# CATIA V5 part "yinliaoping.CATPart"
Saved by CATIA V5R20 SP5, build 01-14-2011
Part number: 饮料瓶
Bounding box of the stored display mesh (mm): x -26 to 26, y -25.976 to 25.977, z 0 to 110
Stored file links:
  E:\180132104于洋\yinliaoping.CATPart
  C:\Program Files\Dassault Systemes\B20\intel_a\startup\materials\Catalog.CATMaterial
  C:\Program Files\Dassault Systemes\B20\intel_a\startup\materials\brushed_metal1.jpg
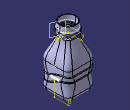
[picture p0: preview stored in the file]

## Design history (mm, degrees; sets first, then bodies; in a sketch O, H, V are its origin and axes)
Set1
  Sketch1 on xy-plane, origin (0, 0, 0), H (1, 0, 0), V (0, 1, 0)
    line L1 (25, 25) -> (25, -25)
    line L2 (25, -25) -> (-25, -25)
    line L3 (-25, -25) -> (-25, 25)
    line L4 (-25, 25) -> (25, 25)
    length L1 = 50
    length L4 = 50
    vertical: L1 V, L3 V
    horizontal: L2 H, L4 H
    equidistance: L1 L3 O, L2 L4 O
  Sketch2 on face of Pad1 from Sketch1.L3, origin (-25, 0, 0), H (0, -1, 0), V (0, 0, 1)
    spline S1 through (-40, 20) (-10, 30) (10, 20) (40, 30)
  Extrude1: Element1 Sketch2, Lim1 60, Lim2 60
  MultiSel1: CommonCtxFeats ({extract ExtractElem face of Pad1 from Sketch1.L3}; {extract ExtractElem face of Fillet1}; {extract ExtractElem face of Pad1 from Sketch1.L2}; {extract ExtractElem face of Fillet1}; {extract ExtractElem face of Pad1 from Sketch1.L1}; {extract ExtractElem face of Fillet1}; {extract ExtractElem face of Pad1 from Sketch1.L4}; {extract ExtractElem face of Fillet1})
  Join1: Elements ({intersect ToIntersect1 {extract ExtractElem face of Pad1 from Sketch1.L1}, ToIntersect2 Extrude1}; {intersect ToIntersect1 {extract ExtractElem face of Fillet1}, ToIntersect2 Extrude1}; {intersect ToIntersect1 {extract ExtractElem face of Pad1 from Sketch1.L4}, ToIntersect2 Extrude1}; {intersect ToIntersect1 {extract ExtractElem face of Fillet1}, ToIntersect2 Extrude1}; {intersect ToIntersect1 {extract ExtractElem face of Pad1 from Sketch1.L3}, ToIntersect2 Extrude1}; {intersect ToIntersect1 {extract ExtractElem face of Fillet1}, ToIntersect2 Extrude1}; {intersect ToIntersect1 {extract ExtractElem face of Pad1 from Sketch1.L2}, ToIntersect2 Extrude1}; {intersect ToIntersect1 {extract ExtractElem face of Fillet1}, ToIntersect2 Extrude1})
  Sketch3 on face of Pad1 from Sketch1.L1, origin (25, 0, 0), H (0, 1, 0), V (0, 0, 1)
    spline S1 through (-40, 40) (-20, 30) (10, 40) (40, 30)
  Extrude2: Element1 Sketch3, Lim1 60, Lim2 60
  MultiSel2: CommonCtxFeats ({extract ExtractElem face of Pad1 from Sketch1.L1}; {extract ExtractElem face of Fillet1}; {extract ExtractElem face of Pad1 from Sketch1.L4}; {extract ExtractElem face of Fillet1}; {extract ExtractElem face of Pad1 from Sketch1.L3}; {extract ExtractElem face of Fillet1}; {extract ExtractElem face of Pad1 from Sketch1.L2}; {extract ExtractElem face of Fillet1})
  Plane1: type Normal, Curve Join1, RefPoint vertex [face of MultiSel1 | face of MultiSel1]
  Circle1: type CtrRad, Start 0, End 180, Center vertex [face of MultiSel1 | face of MultiSel1], Support Plane1, Radius 1, FirstDirection (-1, 0, 0)
  Plane2: type Normal, Curve {intersect ToIntersect1 {extract ExtractElem face of Pad1 from Sketch1.L1}, ToIntersect2 Extrude2}, RefPoint vertex of MultiSel2
Body1 (main body), material "无"
  Pad1: profile Sketch1, direction (0, 0, 1), length 50
  Fillet1: on edge [face of Pad1 from Sketch1.L4 | face of Pad1 from Sketch1.L1]; edge [face of Pad1 from Sketch1.L1 | face of Pad1 from Sketch1.L2]; edge [face of Pad1 from Sketch1.L3 | face of Pad1 from Sketch1.L4]; edge [face of Pad1 from Sketch1.L2 | face of Pad1 from Sketch1.L3]
  Fillet2: on edge [start face of Pad1 | face of Pad1 from Sketch1.L4]
  Plane3: type Offset, RefPlane end face of Pad1, Offset 40, reversed
  Sketch4 on Plane3, origin (0, 0, 90), H (1, 0, 0), V (0, -1, 0)
    circle A1 centre (0, 0) radius 15
  Pad2: profile Sketch4, direction (0, 0, 1), length 20
  Sketch5 on end face of Pad1, origin (0, 0, 50), H (1, 0, 0), V (0, 1, 0)
    point P1 (25, 0)
    distance P1 O = 25
    coincidence: P1 H
  Sketch6 on start face of Pad2, origin (0, 0, 90), H (1, 0, 0), V (0, -1, 0)
    point P1 (15, 0)
    distance P1 O = 15
    coincidence: P1 H
  Loft1: solid, Sections ({boundary Boundary {extract ExtractElem end face of Pad1}}; {boundary Boundary {extract ExtractElem start face of Pad2}}), StartFace end face of Pad1, EndFace start face of Pad2
  Slot1: profile Circle1, centre curve Join1
  Circle2: type CtrRad, Start 0, End 180, Center vertex of MultiSel2, Support Plane2, Radius 1, FirstDirection (1, 0, 0)
  Join2: Elements ({intersect ToIntersect1 {extract ExtractElem face of Pad1 from Sketch1.L1}, ToIntersect2 Extrude2}; {intersect ToIntersect1 {extract ExtractElem face of Fillet1}, ToIntersect2 Extrude2}; {intersect ToIntersect1 {extract ExtractElem face of Pad1 from Sketch1.L4}, ToIntersect2 Extrude2}; {intersect ToIntersect1 {extract ExtractElem face of Fillet1}, ToIntersect2 Extrude2}; {intersect ToIntersect1 {extract ExtractElem face of Pad1 from Sketch1.L3}, ToIntersect2 Extrude2}; {intersect ToIntersect1 {extract ExtractElem face of Fillet1}, ToIntersect2 Extrude2}; {intersect ToIntersect1 {extract ExtractElem face of Pad1 from Sketch1.L2}, ToIntersect2 Extrude2}; {intersect ToIntersect1 {extract ExtractElem face of Fillet1}, ToIntersect2 Extrude2})
  Rib1: profile Circle2, centre curve Join2
  Shell1: ExtOffset 0, Face end face of Pad2, IntOffset 1
  Plane4: type Offset, RefPlane start face of Pad1, Offset 91
  Sketch7 on Plane4, origin (0, 0, 91), H (1, 0, 0), V (0, 1, 0)
  Sketch8 on Plane4, origin (0, 0, 91), H (1, 0, 0), V (0, 1, 0)
    point P1 (15, 0)
    distance P1 O = 15
    coincidence: P1 H
  Helix1: Direction Z axis, RefPoint Sketch8, Pitch 2, Height 10, TaperAngle 0
  Point1: type OnCurve, Support Helix1, RefPoint vertex of Helix1, Length -6
  Line1: type PtDir, RefPoint vertex of Helix1, Direction (1, 0, 0), Start 0, End 10
  Connect1: Curve1 Line1, Point1 vertex of Line1, Tension1 1, Curve2 Helix1, Point2 Point1, Tension2 1
  Point2: type OnCurve, Support Connect1, RefPoint Sketch8, Length -6
  Line2: type PtDir, RefPoint Sketch8, Direction (1, 0, 0), Start 0, End 10
  Connect2: Curve1 Line2, Point1 vertex of Line2, Tension1 1, Curve2 Connect1, Point2 Point2, Tension2 1
Body2
  Sketch9 on face of Pad1 from Sketch1.L1, origin (25, 0, 0), H (0, 1, 0), V (0, 0, 1)
    polyline C1
    polyline C2
    polyline C3
    polyline C4
    polyline C5
    polyline C6
    polyline C7
    polyline C8
    polyline C9
    polyline C10
    polyline C11
    polyline C12
  Plane5: type Normal, Curve Connect2, RefPoint Point1
  Circle3: type CtrRad, Start 0, End 180, Center Point1, Support Plane5, Radius 2, FirstDirection (-0.9211, 0.3893, 0)
  Rib2: profile Circle3, centre curve Connect2
  Sketch10 on face of Pad1 from Sketch1.L1, origin (25, 0, 0), H (0, 1, 0), V (0, 0, 1)
  Sketch11 on Plane4, origin (0, 0, 91), H (1, 0, 0), V (0, 1, 0)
